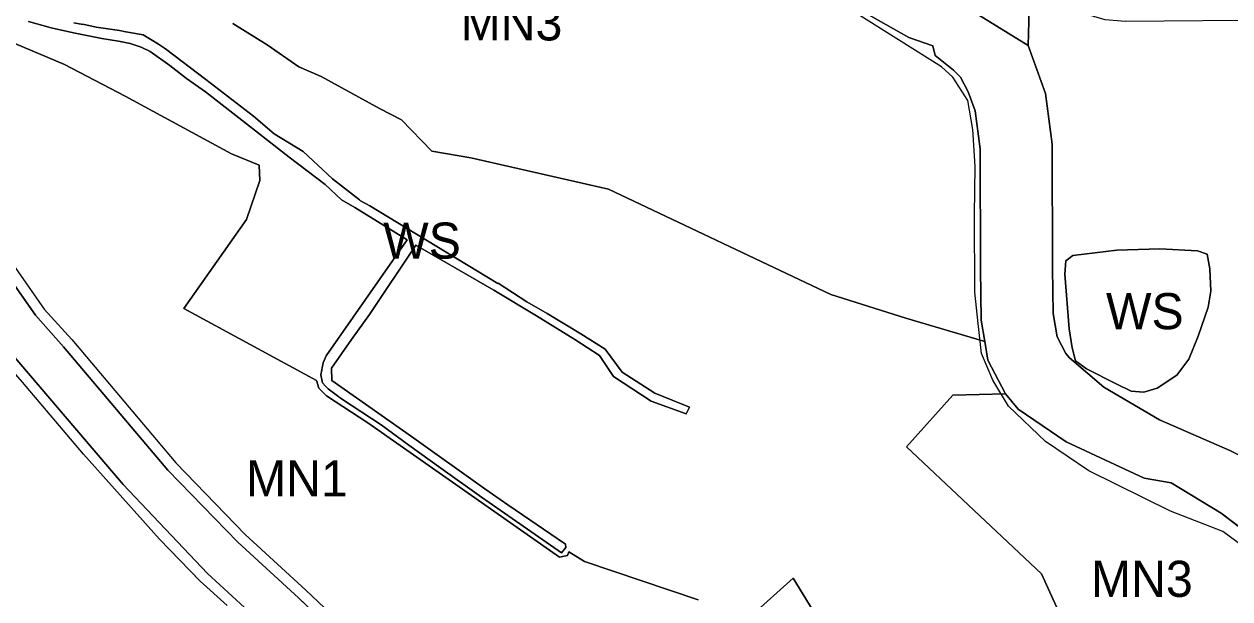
# Model space of a CAD drawing. Extents: x 7417187 to 7419415, y 5539178 to 5540826.
# Drawn here: x 7418400.2 to 7418734.7, y 5539771.1 to 5539930.4 of the extents above; entities that cross this region are included whole.
import ezdxf

# ---------------------------------------------------------------- set-up
doc = ezdxf.new("R2010")
doc.units = 0
for name, color, linetype in [('linie_rozgraniczajace', 7, 'Continuous'), ('linie_zabudowy_nieprzekraczalne', 7, 'Continuous'), ('oznaczenia_przeznaczen', 7, 'Continuous')]:
    doc.layers.add(name, color=color, linetype=linetype)

msp = doc.modelspace()

# ---------------------------------------------------------------- linework, layer by layer
at = {"layer": 'linie_rozgraniczajace'}
for p, q in [((7418645.61, 5539926.63), (7418632.89, 5539933.88)), ((7418660.83, 5539935.45), (7418678.67, 5539924.49)), ((7418652.25, 5539924.41), (7418645.61, 5539926.63)), ((7418652.93, 5539921.69), (7418652.25, 5539924.41)), ((7418678.67, 5539924.49), (7418683.53, 5539911.12)), ((7418658.04, 5539917.65), (7418652.93, 5539921.69)), ((7418659.98, 5539915.68), (7418658.04, 5539917.65)), ((7418662.08, 5539911.58), (7418659.98, 5539915.68)), ((7418663.98, 5539906.35), (7418662.08, 5539911.58)), ((7418683.53, 5539911.12), (7418685.36, 5539897.14)), ((7418665.36, 5539895.81), (7418663.98, 5539906.35)), ((7418685.36, 5539897.14), (7418685.47, 5539862.78)), ((7418665.47, 5539862.58), (7418665.36, 5539895.81)), ((7418392.53, 5539865.18), (7418403.36, 5539849.67)), ((7418665.71, 5539848.35), (7418665.47, 5539862.58)), ((7418685.47, 5539862.78), (7418685.68, 5539850.17)), ((7418685.68, 5539850.17), (7418686.76, 5539843.67)), ((7418403.36, 5539849.67), (7418411.16, 5539840.97)), ((7418666.7, 5539842.4), (7418665.71, 5539848.35)), ((7418686.76, 5539843.67), (7418689.12, 5539839.11)), ((7418427.7, 5539802.79), (7418393.93, 5539842.31)), ((7418411.16, 5539840.97), (7418440.09, 5539806.73)), ((7418667.55, 5539837.28), (7418666.7, 5539842.4)), ((7418672.39, 5539827.92), (7418667.55, 5539837.28)), ((7418689.12, 5539839.11), (7418690.19, 5539837.84)), ((7418690.19, 5539837.84), (7418699.69, 5539829.75)), ((7418675.97, 5539823.68), (7418672.39, 5539827.92)), ((7418699.69, 5539829.75), (7418715.09, 5539820.74)), ((7418689.24, 5539814.6), (7418675.97, 5539823.68)), ((7418715.09, 5539820.74), (7418734.61, 5539812.19)), ((7418710.86, 5539804.53), (7418689.24, 5539814.6)), ((7418734.61, 5539812.19), (7418744.21, 5539807.3)), ((7418440.09, 5539806.73), (7418459.5, 5539786.75)), ((7418718.37, 5539803.19), (7418710.86, 5539804.53)), ((7418451.14, 5539778.14), (7418427.7, 5539802.79)), ((7418732.26, 5539794.78), (7418718.37, 5539803.19)), ((7418747.18, 5539783.41), (7418732.26, 5539794.78)), ((7418459.5, 5539786.75), (7418476.33, 5539771.33)), ((7418461.39, 5539768.7), (7418451.14, 5539778.14)), ((7418476.33, 5539771.33), (7418491.86, 5539756.55))]:
    msp.add_line(p, q, dxfattribs=at)
for points in [[(7418744.21, 5539807.3), (7418734.61, 5539812.19), (7418715.09, 5539820.74), (7418699.69, 5539829.75), (7418690.19, 5539837.84), (7418689.12, 5539839.11), (7418686.76, 5539843.67), (7418685.68, 5539850.17), (7418685.47, 5539862.78), (7418685.36, 5539897.14), (7418683.53, 5539911.12), (7418678.67, 5539924.49), (7418678.94, 5539934.48), (7418680.58, 5539937.78), (7418695.21, 5539933.05), (7418699.93, 5539931.66), (7418705.75, 5539931.19), (7418748.43, 5539931.6)], [(7418632.89, 5539933.88), (7418645.61, 5539926.63), (7418652.25, 5539924.41), (7418652.93, 5539921.69), (7418658.04, 5539917.65), (7418659.98, 5539915.68), (7418662.08, 5539911.58), (7418663.98, 5539906.35), (7418665.36, 5539895.81), (7418665.47, 5539862.58), (7418665.71, 5539848.35), (7418666.7, 5539842.4), (7418644.78, 5539848.9), (7418623.97, 5539855.47), (7418562.36, 5539884.65), (7418524.18, 5539893.29), (7418513.3, 5539895.21), (7418504.89, 5539903.89), (7418498.8, 5539906.96), (7418482.64, 5539915.86), (7418476.43, 5539918.53), (7418467.69, 5539924.67), (7418458.16, 5539930.52)], [(7418678.94, 5539934.48), (7418678.67, 5539924.49), (7418660.83, 5539935.45)], [(7418414.01, 5539930.78), (7418416.54, 5539930.27), (7418416.54, 5539930.38), (7418420.25, 5539929.52), (7418426.67, 5539928.58), (7418428.41, 5539928.21), (7418433.28, 5539927.43), (7418437.48, 5539924.83), (7418439.46, 5539923.58), (7418450.62, 5539915.04), (7418463.9, 5539904.88), (7418469.61, 5539900.01), (7418477.64, 5539895.12), (7418485.77, 5539887.53), (7418493.29, 5539881.7), (7418493.26, 5539881.64), (7418493.57, 5539881.4), (7418496.08, 5539880.02), (7418509.06, 5539872.15), (7418531.66, 5539858.45), (7418531.72, 5539858.55), (7418539.69, 5539853.38), (7418545.29, 5539850.17), (7418554.61, 5539844.58), (7418561.38, 5539840.26), (7418566.09, 5539833.9), (7418575.19, 5539828.05), (7418584.8, 5539824.25), (7418583.84, 5539822.32), (7418574.17, 5539825.9), (7418563.74, 5539832.71), (7418559.8, 5539838.55), (7418553, 5539842.93), (7418542.38, 5539849.53), (7418530.48, 5539856.68), (7418508.9, 5539869.13), (7418496.04, 5539849.85), (7418491.06, 5539842.99), (7418485.5, 5539835.02), (7418485.63, 5539831.6), (7418501.73, 5539820.21), (7418507.67, 5539816.04), (7418527.98, 5539801.54), (7418534.37, 5539797.18), (7418550.41, 5539786.24), (7418550.44, 5539785.29), (7418549.29, 5539783.83), (7418535.58, 5539793.38), (7418527.13, 5539799.27), (7418515.79, 5539807.26), (7418506.96, 5539813.65), (7418499.23, 5539819.35), (7418488.27, 5539826.53), (7418484.58, 5539829.29), (7418483.93, 5539829.97), (7418483.03, 5539830.91), (7418482.53, 5539833.19), (7418483.14, 5539836.52), (7418484, 5539838.45), (7418506.47, 5539870.63), (7418491.98, 5539879.58), (7418488.29, 5539881.72), (7418483.74, 5539885.96), (7418473.78, 5539893.5), (7418463.6, 5539901.49), (7418450.54, 5539911.61), (7418445.31, 5539915.3), (7418440.63, 5539918.89), (7418435.22, 5539922.83), (7418432.69, 5539923.98), (7418429.64, 5539924.99), (7418426.41, 5539925.65), (7418421.81, 5539926.39), (7418413.98, 5539927.95), (7418407.77, 5539929.32), (7418401.48, 5539931.12)], [(7418401.48, 5539931.12), (7418407.77, 5539929.32), (7418413.98, 5539927.95), (7418421.81, 5539926.39), (7418426.41, 5539925.65), (7418429.64, 5539924.99), (7418432.69, 5539923.98), (7418435.22, 5539922.83), (7418440.63, 5539918.89), (7418445.31, 5539915.3), (7418450.54, 5539911.61), (7418463.6, 5539901.49), (7418473.78, 5539893.5), (7418483.74, 5539885.96), (7418488.29, 5539881.72), (7418491.98, 5539879.58), (7418506.47, 5539870.63), (7418484, 5539838.45), (7418483.14, 5539836.52), (7418482.53, 5539833.19), (7418483.03, 5539830.91), (7418483.93, 5539829.97), (7418484.58, 5539829.29), (7418488.27, 5539826.53), (7418499.23, 5539819.35), (7418506.96, 5539813.65), (7418515.79, 5539807.26), (7418527.13, 5539799.27), (7418535.58, 5539793.38), (7418549.29, 5539783.83), (7418550.44, 5539785.29), (7418550.41, 5539786.24), (7418534.37, 5539797.18), (7418527.98, 5539801.54), (7418507.67, 5539816.04), (7418501.73, 5539820.21), (7418485.63, 5539831.6), (7418485.5, 5539835.02), (7418491.06, 5539842.99), (7418496.04, 5539849.85), (7418508.9, 5539869.13), (7418530.48, 5539856.68), (7418542.38, 5539849.53), (7418553, 5539842.93), (7418559.8, 5539838.55), (7418563.74, 5539832.71), (7418574.17, 5539825.9), (7418583.84, 5539822.32), (7418584.8, 5539824.25), (7418575.19, 5539828.05), (7418566.09, 5539833.9), (7418561.38, 5539840.26), (7418554.61, 5539844.58), (7418545.29, 5539850.17), (7418539.69, 5539853.38), (7418531.72, 5539858.55), (7418531.66, 5539858.45), (7418509.06, 5539872.15), (7418496.08, 5539880.02), (7418493.57, 5539881.4), (7418493.26, 5539881.64), (7418493.29, 5539881.7), (7418485.77, 5539887.53), (7418477.64, 5539895.12), (7418469.61, 5539900.01), (7418463.9, 5539904.88), (7418450.62, 5539915.04), (7418439.46, 5539923.58), (7418437.48, 5539924.83), (7418433.28, 5539927.43), (7418428.41, 5539928.21), (7418426.67, 5539928.58), (7418420.25, 5539929.52), (7418416.54, 5539930.38), (7418416.54, 5539930.27), (7418414.01, 5539930.78)], [(7418458.16, 5539930.52), (7418467.69, 5539924.67), (7418476.43, 5539918.53), (7418482.64, 5539915.86), (7418498.8, 5539906.96), (7418504.89, 5539903.89), (7418513.3, 5539895.21), (7418524.18, 5539893.29), (7418562.36, 5539884.65), (7418623.97, 5539855.47), (7418644.78, 5539848.9), (7418666.7, 5539842.4), (7418667.55, 5539837.28), (7418672.39, 5539827.92), (7418657.8, 5539827.5), (7418644.96, 5539813.17), (7418682.41, 5539778.05), (7418695.68, 5539748.68)], [(7418397.68, 5539924.98), (7418411.41, 5539919.15), (7418428.27, 5539910.44), (7418457.77, 5539894.41), (7418465.46, 5539891.27), (7418465.63, 5539887.03), (7418461.96, 5539876.27), (7418444.57, 5539851.6), (7418481.31, 5539831.63), (7418481.98, 5539829.49), (7418484.13, 5539827.38), (7418495.55, 5539819.85), (7418548.77, 5539782.61), (7418550.91, 5539783.09), (7418551.33, 5539784.09), (7418555.64, 5539781.44), (7418587.17, 5539770.77)], [(7418587.17, 5539770.77), (7418555.64, 5539781.44), (7418551.33, 5539784.09), (7418550.91, 5539783.09), (7418548.77, 5539782.61), (7418495.55, 5539819.85), (7418484.13, 5539827.38), (7418481.98, 5539829.49), (7418481.31, 5539831.63), (7418444.57, 5539851.6), (7418461.96, 5539876.27), (7418465.63, 5539887.03), (7418465.46, 5539891.27), (7418457.77, 5539894.41), (7418428.27, 5539910.44), (7418411.41, 5539919.15), (7418397.68, 5539924.98)], [(7418491.86, 5539756.55), (7418476.33, 5539771.33), (7418459.5, 5539786.75), (7418440.09, 5539806.73), (7418411.16, 5539840.97), (7418403.36, 5539849.67), (7418392.53, 5539865.18)], [(7418393.93, 5539842.31), (7418427.7, 5539802.79), (7418451.14, 5539778.14), (7418461.39, 5539768.7), (7418464.15, 5539760.11), (7418458.68, 5539720.6), (7418453.49, 5539682.96), (7418447.59, 5539640.03), (7418441.73, 5539598.41), (7418379.39, 5539602.6)], [(7418736.92, 5539715.13), (7418726.22, 5539710.49), (7418715.48, 5539729.82), (7418710.25, 5539727.38), (7418709.84, 5539728.16), (7418712.08, 5539739.56), (7418704.78, 5539754.37), (7418695.68, 5539748.68), (7418682.41, 5539778.05), (7418644.96, 5539813.17), (7418657.8, 5539827.5), (7418672.39, 5539827.92), (7418675.97, 5539823.68), (7418689.24, 5539814.6), (7418710.86, 5539804.53), (7418718.37, 5539803.19), (7418732.26, 5539794.78), (7418747.18, 5539783.41)], [(7418601.79, 5539766.3), (7418613.5, 5539776.82), (7418640.23, 5539733.18)], [(7418640.23, 5539733.18), (7418613.5, 5539776.82), (7418601.79, 5539766.3)]]:
    msp.add_lwpolyline(points, dxfattribs=at)
for points in [[(7418714.44, 5539829.5), (7418710.78, 5539828.41), (7418707.23, 5539828.63), (7418703.14, 5539830.63), (7418694.9, 5539834.85), (7418691.87, 5539837.06), (7418690.91, 5539840.64), (7418690.08, 5539845.95), (7418688.9, 5539861.07), (7418689.12, 5539864.8), (7418691.06, 5539866.23), (7418703.28, 5539867.74), (7418715.19, 5539868.06), (7418725.63, 5539867.5), (7418728.39, 5539866.59), (7418729.08, 5539862.53), (7418729.41, 5539856.36), (7418728.66, 5539851.93), (7418725.88, 5539843.87), (7418723.25, 5539837.53), (7418719.93, 5539833.06)], [(7418714.44, 5539829.5), (7418719.93, 5539833.06), (7418723.25, 5539837.53), (7418725.88, 5539843.87), (7418728.66, 5539851.93), (7418729.41, 5539856.36), (7418729.08, 5539862.53), (7418728.39, 5539866.59), (7418725.63, 5539867.5), (7418715.19, 5539868.06), (7418703.28, 5539867.74), (7418691.06, 5539866.23), (7418689.12, 5539864.8), (7418688.9, 5539861.07), (7418690.08, 5539845.95), (7418690.91, 5539840.64), (7418691.87, 5539837.06), (7418694.9, 5539834.85), (7418703.14, 5539830.63), (7418707.23, 5539828.63), (7418710.78, 5539828.41)]]:
    msp.add_lwpolyline(points, close=True, dxfattribs=at)
at = {"layer": 'linie_zabudowy_nieprzekraczalne'}
for points in [[(7418743.65, 5539781.72), (7418732.71, 5539789.72), (7418718.2, 5539795.35), (7418695.52, 5539806.58), (7418683.5, 5539814.72), (7418673.26, 5539824.44), (7418668.9, 5539831.72), (7418665.77, 5539839.04), (7418664.81, 5539847.37), (7418663.93, 5539856.06), (7418663.81, 5539877.54), (7418663.99, 5539890.95), (7418663.35, 5539901.13), (7418661.94, 5539909.17), (7418657.79, 5539915.64), (7418654.7, 5539918.55), (7418638.78, 5539928.55), (7418626.03, 5539936.56)], [(7418383.45, 5539924.86), (7418387.11, 5539920.73), (7418389.54, 5539915.69), (7418390.31, 5539910.44), (7418390.13, 5539906.53), (7418389.84, 5539897.91), (7418390.26, 5539883.83), (7418390.66, 5539872.96), (7418394.98, 5539866.91), (7418405.82, 5539851.39)], [(7418405.82, 5539851.39), (7418413.43, 5539842.93), (7418442.31, 5539808.75), (7418461.59, 5539788.91), (7418478.38, 5539773.52), (7418493.9, 5539758.76), (7418516.3, 5539738.65), (7418534.25, 5539722.94), (7418534.72, 5539723.11)], [(7418416.72, 5539811.15), (7418399.82, 5539831.15), (7418391.53, 5539840.5)], [(7418437.77, 5539787.6), (7418416.72, 5539811.15)], [(7418456.52, 5539769.2), (7418449.05, 5539775.99), (7418437.77, 5539787.6)]]:
    msp.add_lwpolyline(points, dxfattribs=at)

# ---------------------------------------------------------------- texts
at = {"layer": 'oznaczenia_przeznaczen'}
for s, p in [('MN3', (7418521.29, 5539925.86)), ('WS', (7418499.83, 5539865.38)), ('WS', (7418700.29, 5539845.82)), ('MN1', (7418461.77, 5539799.46)), ('MN3', (7418696.12, 5539771.63))]:
    msp.add_text(s, height=10, dxfattribs=at).set_placement(p)

doc.saveas('drawing.dxf')
